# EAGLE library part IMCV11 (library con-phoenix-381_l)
Invertierter Mini-Combicon 3.81mm vertikal 11-polig IMCV 1,5/11-G-3,81 (ohne Gegenstecker)
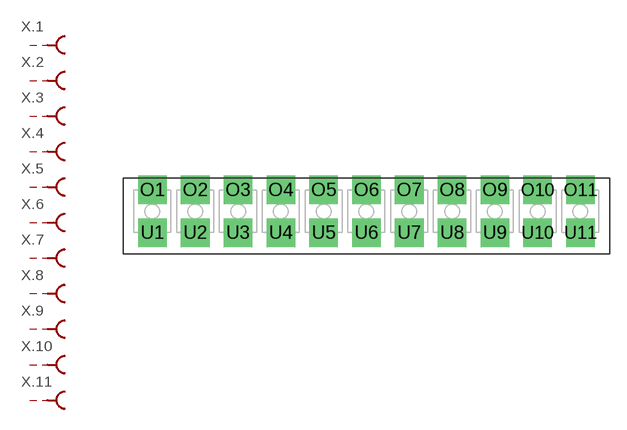
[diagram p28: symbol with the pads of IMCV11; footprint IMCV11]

Designator prefix X; gates .6=MCBU .5=MCBU .4=MCBU .3=MCBU .2=MCBU .1=MCBU .7=MCBU .8=MCBU .9=MCBU .10=MCBU .11=MCBU

## IMCV11  [IMCV11]
O1  .1:S  pas
O2  .2:S  pas
O3  .3:S  pas
O4  .4:S  pas
O5  .5:S  pas
O6  .6:S  pas
O7  .7:S  pas
O8  .8:S  pas
O9  .9:S  pas
O10  .10:S  pas
O11  .11:S  pas
U1  .1:SK  pas
U2  .2:SK  pas
U3  .3:SK  pas
U4  .4:SK  pas
U5  .5:SK  pas
U6  .6:SK  pas
U7  .7:SK  pas
U8  .8:SK  pas
U9  .9:SK  pas
U10  .10:SK  pas
U11  .11:SK  pas

## Footprint IMCV11 (pad centres in mm)
Mini-Combicon 3.81mm vertical 11-polig invertiert (ohne Gegenstecker)
drill 1.3 pad 2.54 square: O1 -19.05,1.905; O2 -15.24,1.905; O3 -11.43,1.905; O4 -7.62,1.905; O5 -3.81,1.905; O6 0,1.905; O7 3.81,1.905; O8 7.62,1.905; O9 11.43,1.905; O10 15.24,1.905; O11 19.05,1.905; U1 -19.05,-1.905; U2 -15.24,-1.905; U3 -11.43,-1.905; U4 -7.62,-1.905; U5 -3.81,-1.905; U6 0,-1.905; U7 3.81,-1.905; U8 7.62,-1.905; U9 11.43,-1.905; U10 15.24,-1.905; U11 19.05,-1.905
